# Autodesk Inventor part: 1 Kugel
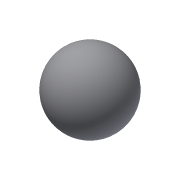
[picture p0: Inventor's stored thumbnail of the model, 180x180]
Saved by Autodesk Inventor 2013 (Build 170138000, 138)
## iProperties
Created: 2012-10
Part Number: 1 Kugel
Material: Allgemein
Vendor: www.inventor-faq.de
Document SubType Name: Modeling
Designer: Administrator
Manufacturer: www.inventor-faq.de
Density: 1 g/cm^3
RuleStatus: InUse
AfterDocOpen0: inventorfaq
BeforeDocSave0: inventorfaq
Author: Administrator
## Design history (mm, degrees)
sketch "Skizze1"
  geometry: L1 (3.947, 3.07)-(-3.947, -3.07); A1 r 5 centre (0, 0) between (3.947, 3.07) and (-3.947, -3.07); 1 further point
  constraints: 2 end point, 2 point on circle, 1 centre point, 1 coincident, 1 midpoint
  dimensions: "d0" = 10 diameter of A1
revolve "Umdrehung1" sketch "Skizze1" stored, may be unused: angle "d1" = 90 deg
node "Volumenkörper1"
